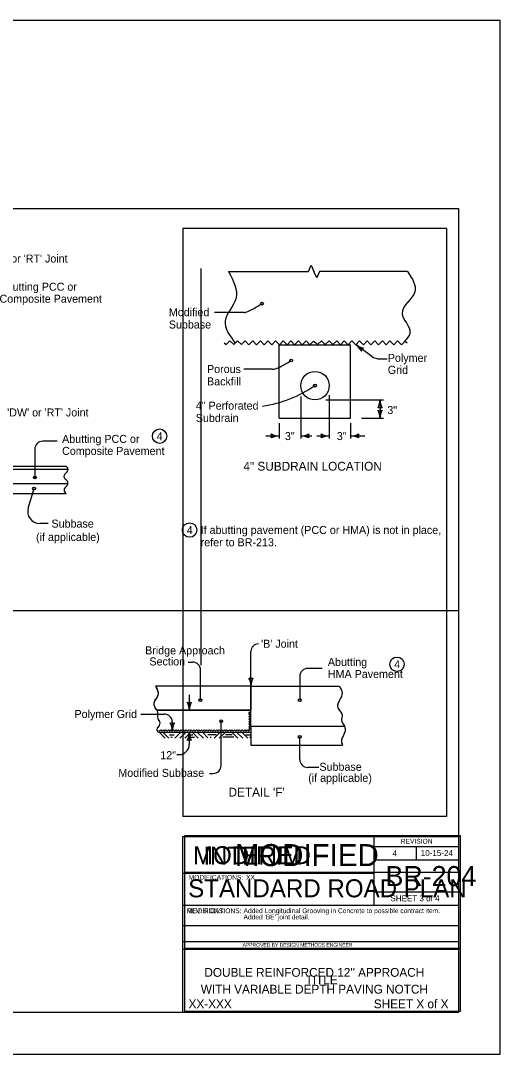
# Model space of a CAD drawing. Extents: x -2135039 to -2120895, y -2139150 to -2136566.
# Drawn here: x -2125693 to -2124495, y -2139150 to -2136566 of the extents above; entities that cross this region are included whole.
import ezdxf

# ---------------------------------------------------------------- set-up
doc = ezdxf.new("R2010")
doc.units = 0
for name, color, linetype in [('dsnDOTLogo', 7, 'Continuous'), ('dsnNonPlotable', 7, 'Continuous'), ('dsnStdBlock', 7, 'Continuous'), ('dsnstdblockInterim', 7, 'Continuous'), ('dsnStdLabel', 7, 'Continuous'), ('dsnStdLineWork', 7, 'Continuous'), ('dsnStdLogo', 7, 'Continuous'), ('dsnstdModifiedBlock', 7, 'Continuous'), ('dsnStdNote', 7, 'Continuous'), ('Level 1', 7, 'Continuous'), ('Level 2', 7, 'Continuous'), ('Level 3', 7, 'Continuous')]:
    doc.layers.add(name, color=color, linetype=linetype)

msp = doc.modelspace()

# ---------------------------------------------------------------- linework, layer by layer
at = {"layer": 'dsnDOTLogo'}
msp.add_lwpolyline([(-2127839, -2139150.4), (-2124495, -2139150.4), (-2124495, -2136566.4), (-2127839, -2136566.4)], close=True, dxfattribs=at)
at = {"layer": 'dsnNonPlotable'}
for p, q in [((-2125287.5, -2137085.9), (-2125287.5, -2138555.9)), ((-2124629.5, -2137085.9), (-2125287.5, -2137085.9)), ((-2124629.5, -2137085.9), (-2124629.5, -2138555.9)), ((-2125242.5, -2137185.9), (-2125242.5, -2138177.5)), ((-2127734.5, -2138040.9), (-2124599.5, -2138040.9)), ((-2124629.5, -2138555.9), (-2125287.5, -2138555.9))]:
    msp.add_line(p, q, dxfattribs=at)
at = {"layer": 'dsnStdLabel'}
for p, q in [((-2125601.3, -2137617.9), (-2125637.8, -2137617.9)), ((-2125657.6, -2137637.7), (-2125657.6, -2137709)), ((-2125673.9, -2137785), (-2125659.4, -2137736.1)), ((-2125623.8, -2137823.2), (-2125645.5, -2137823.2)), ((-2125117.7, -2138229.8), (-2125117.7, -2138143)), ((-2125274.1, -2138170), (-2125263.4, -2138170)), ((-2125243.6, -2138265), (-2125243.6, -2138189.8)), ((-2124939.7, -2138185.9), (-2124976.1, -2138185.9)), ((-2124995.9, -2138205.7), (-2124995.9, -2138265)), ((-2125271.8, -2138251.9), (-2125271.8, -2138290.3)), ((-2125392.4, -2138299.9), (-2125333.9, -2138299.9)), ((-2125314.1, -2138319.7), (-2125314.1, -2138341.9)), ((-2125192.1, -2138428.4), (-2125192.1, -2138317.9)), ((-2125271.8, -2138345.9), (-2125271.8, -2138376.1)), ((-2124995.9, -2138413.4), (-2124995.9, -2138357)), ((-2125302.5, -2138401.1), (-2125296.8, -2138401.1)), ((-2124948.1, -2138433.2), (-2124976.1, -2138433.2)), ((-2125221, -2138448.2), (-2125211.9, -2138448.2))]:
    msp.add_line(p, q, dxfattribs=at)
for centre in [(-2125657.6, -2137708.4), (-2125659.4, -2137736.1), (-2125244, -2138265), (-2124995.9, -2138265), (-2125192.1, -2138317.9), (-2124995.9, -2138357)]:
    msp.add_circle(centre, 3.46, dxfattribs=at)
for centre, radius, start, end in [((-2124881.3, -2137410.4), 42.5, 25.1788, 53.2513), ((-2124830.5, -2137342.2), 42.5, 233.2513, 261.3238), ((-2124827.4, -2137397.6), 16.4, 125.5179, 160.9846), ((-2125637.8, -2137637.7), 19.8, 90, 180), ((-2125645.5, -2137793.5), 29.7, 163.4172, 270), ((-2125099.2, -2138143), 18.6, 90, 180), ((-2125263.4, -2138189.8), 19.8, 0, 90), ((-2124976.1, -2138205.7), 19.8, 90, 180), ((-2125117.7, -2138193.9), 16.5, 252.2666, 287.7333), ((-2125160.5, -2138229.8), 42.7, 360, 28.0725), ((-2125117.7, -2138193.9), 16.5, 252.2666, 287.7333), ((-2125160.5, -2138229.8), 42.7, 360, 28.0725), ((-2125075, -2138229.8), 42.7, 151.9275, 180), ((-2125075, -2138229.8), 42.7, 151.9275, 180), ((-2125271.8, -2138254.5), 16.5, 252.2666, 287.7333), ((-2125314.6, -2138290.3), 42.7, 360, 28.0725), ((-2125229.1, -2138290.3), 42.7, 151.9275, 180), ((-2125333.9, -2138319.7), 19.8, 0, 90), ((-2125314.1, -2138306.1), 16.5, 252.2667, 287.7334), ((-2125356.8, -2138341.9), 42.7, 0, 28.0725), ((-2125271.3, -2138341.9), 42.7, 151.9275, 180), ((-2125314.6, -2138345.9), 42.7, 331.9275, 360), ((-2125229.1, -2138345.9), 42.7, 180, 208.0725), ((-2125271.8, -2138381.8), 16.5, 72.2666, 107.7334), ((-2125211.9, -2138428.4), 19.8, 270, 360), ((-2124976.1, -2138413.4), 19.8, 180, 270)]:
    msp.add_arc(centre, radius, start, end, dxfattribs=at)
at = {"layer": 'dsnStdLineWork'}
for p, q in [((-2125750.3, -2137679.9), (-2125579.5, -2137679.9)), ((-2125750.3, -2137688), (-2125574.6, -2137688)), ((-2125574.7, -2137724.5), (-2125750.3, -2137724.5)), ((-2125750.3, -2137748.2), (-2125579.5, -2137748.2)), ((-2125117.7, -2138230.3), (-2125355.8, -2138230.3)), ((-2125117.7, -2138230.3), (-2124896.8, -2138230.3)), ((-2125117.7, -2138230.3), (-2125117.7, -2138290.3)), ((-2125117.7, -2138290.3), (-2125352.7, -2138290.3)), ((-2125117.7, -2138330.3), (-2125117.7, -2138290.3)), ((-2125117.7, -2138330.3), (-2124883.9, -2138330.3)), ((-2125117.7, -2138330.3), (-2125117.7, -2138377.6)), ((-2125118.2, -2138346.2), (-2125345.7, -2138346.2)), ((-2125345.7, -2138346.2), (-2125331.7, -2138360.2)), ((-2125336.7, -2138346.2), (-2125322.7, -2138360.2)), ((-2125309.2, -2138352.4), (-2125321.1, -2138352.4)), ((-2125317.6, -2138357.3), (-2125314.4, -2138357.3)), ((-2125216.7, -2138346.2), (-2125315.3, -2138346.2)), ((-2125293.9, -2138346.2), (-2125307.9, -2138360.2)), ((-2125281.5, -2138346.4), (-2125295.5, -2138360.4)), ((-2125268.7, -2138346.2), (-2125282.7, -2138360.2)), ((-2125273, -2138357.4), (-2125259, -2138357.4)), ((-2125269.2, -2138351.6), (-2125262.8, -2138351.6)), ((-2125263.3, -2138346.2), (-2125249.3, -2138360.2)), ((-2125250.4, -2138346.4), (-2125236.4, -2138360.4)), ((-2125238.1, -2138346.2), (-2125225.3, -2138359)), ((-2125204.8, -2138351.6), (-2125225, -2138351.6)), ((-2125219.9, -2138357.3), (-2125216.7, -2138357.3)), ((-2125195.3, -2138346.2), (-2125209.3, -2138360.2)), ((-2125183, -2138346.4), (-2125197, -2138360.4)), ((-2125160.4, -2138357.4), (-2125188.2, -2138357.4)), ((-2125164.2, -2138351.6), (-2125181.3, -2138351.6)), ((-2125164.8, -2138346.2), (-2125150.8, -2138360.2)), ((-2125151.9, -2138346.4), (-2125137.9, -2138360.4)), ((-2125139.5, -2138346.2), (-2125125.6, -2138360.2)), ((-2125130.1, -2138351.6), (-2125118.2, -2138351.6)), ((-2125121.4, -2138357.3), (-2125118.2, -2138357.3)), ((-2125117.7, -2138377.6), (-2124888.9, -2138377.6))]:
    msp.add_line(p, q, dxfattribs=at)
for points in [[(-2125120.5, -2138296.9), (-2125123.1, -2138294.3)], [(-2125121, -2138339.8), (-2125122.8, -2138337.9), (-2125119.7, -2138334.7), (-2125122.8, -2138331.5), (-2125119.7, -2138328.4), (-2125122.8, -2138325.2), (-2125119.6, -2138322), (-2125122.8, -2138318.9), (-2125119.6, -2138315.7), (-2125122.8, -2138312.5), (-2125119.6, -2138309.4), (-2125122.8, -2138306.2), (-2125119.6, -2138303), (-2125122.8, -2138299.9), (-2125120.5, -2138296.9)], [(-2125347.5, -2138340.8), (-2125346, -2138342.4), (-2125342.8, -2138339.2), (-2125339.6, -2138342.4), (-2125336.4, -2138339.2), (-2125333.3, -2138342.4), (-2125330.1, -2138339.3), (-2125326.9, -2138342.4), (-2125323.8, -2138339.3), (-2125320.6, -2138342.5), (-2125317.4, -2138339.3), (-2125314.3, -2138342.5), (-2125311.1, -2138339.3), (-2125307.9, -2138342.5), (-2125304.8, -2138339.3), (-2125301.6, -2138342.5), (-2125298.4, -2138339.3), (-2125295.3, -2138342.5), (-2125292.1, -2138339.4), (-2125288.9, -2138342.5), (-2125285.8, -2138339.4), (-2125282.6, -2138342.5), (-2125279.4, -2138339.4), (-2125276.3, -2138342.6), (-2125273.1, -2138339.4), (-2125271.7, -2138340.5)], [(-2125271.3, -2138340.9), (-2125269.7, -2138342.5), (-2125266.6, -2138339.4), (-2125263.4, -2138342.5), (-2125260.2, -2138339.4), (-2125257.1, -2138342.6), (-2125253.9, -2138339.4), (-2125250.7, -2138342.6), (-2125247.5, -2138339.4), (-2125244.4, -2138342.6), (-2125241.2, -2138339.4), (-2125238.1, -2138342.6), (-2125234.9, -2138339.4), (-2125231.7, -2138342.6), (-2125228.5, -2138339.5), (-2125225.4, -2138342.6), (-2125222.2, -2138339.5), (-2125219, -2138342.7), (-2125215.9, -2138339.5), (-2125212.7, -2138342.7), (-2125209.5, -2138339.5), (-2125206.4, -2138342.7), (-2125203.2, -2138339.5), (-2125200, -2138342.7), (-2125196.9, -2138339.5), (-2125195.1, -2138341)], [(-2125195.1, -2138341), (-2125193.5, -2138342.5), (-2125190.3, -2138339.4), (-2125187.1, -2138342.6), (-2125184, -2138339.4), (-2125180.8, -2138342.6), (-2125177.6, -2138339.4), (-2125174.5, -2138342.6), (-2125171.3, -2138339.4), (-2125168.1, -2138342.6), (-2125165, -2138339.4), (-2125161.8, -2138342.6), (-2125158.6, -2138339.5), (-2125155.5, -2138342.6), (-2125152.3, -2138339.5), (-2125149.1, -2138342.7), (-2125145.9, -2138339.5), (-2125142.8, -2138342.7), (-2125139.6, -2138339.5), (-2125136.5, -2138342.7), (-2125133.3, -2138339.5), (-2125130.1, -2138342.7), (-2125126.9, -2138339.6), (-2125123.8, -2138342.7), (-2125120.9, -2138339.8)]]:
    msp.add_lwpolyline(points, dxfattribs=at)
for points in [[(-2125355.8, -2138229.5), (-2125349.7, -2138244.8), (-2125349.8, -2138251.8), (-2125359.6, -2138271), (-2125358.2, -2138282.3), (-2125351.7, -2138292.4), (-2125351.1, -2138307.9), (-2125345.7, -2138318.8)], [(-2124896.8, -2138230.3), (-2124890.2, -2138246.7), (-2124896.3, -2138264.9), (-2124900.9, -2138274.8), (-2124899.4, -2138287), (-2124889.5, -2138303.7), (-2124891.8, -2138314.4), (-2124883.9, -2138330.3), (-2124887.2, -2138354.7), (-2124891.8, -2138365.3), (-2124888.9, -2138377.6)], [(-2125345.7, -2138318.8), (-2125345.7, -2138325.3), (-2125352.2, -2138335.5)], [(-2125352.2, -2138335.5), (-2125352.2, -2138341.9), (-2125345.7, -2138346.2)]]:
    msp.add_spline(points, degree=3, dxfattribs=at)
at = {"layer": 'dsnStdLogo'}
for p, q in [((-2124810.4, -2138605.9), (-2124810.4, -2138697.3)), ((-2124810.4, -2138630.9), (-2124599.5, -2138630.9)), ((-2124704.9, -2138630.9), (-2124704.9, -2138664.1)), ((-2124810.4, -2138664.1), (-2124599.5, -2138664.1)), ((-2125287.5, -2138697.3), (-2124810.4, -2138697.3)), ((-2124810.4, -2138697.3), (-2124810.4, -2138777.3)), ((-2124599.5, -2138745.1), (-2124810.4, -2138745.1)), ((-2125287.5, -2138777.3), (-2124599.5, -2138777.3)), ((-2125287.5, -2138828.3), (-2124599.5, -2138828.3)), ((-2125287.5, -2138868.3), (-2124599.5, -2138868.3)), ((-2125287.5, -2138887.3), (-2124599.5, -2138887.3))]:
    msp.add_line(p, q, dxfattribs=at)
msp.add_lwpolyline([(-2125287.5, -2138605.9), (-2124599.5, -2138605.9), (-2124599.5, -2139045.9), (-2125287.5, -2139045.9)], close=True, dxfattribs=at)
at = {"layer": 'dsnstdModifiedBlock'}
for p, q in [((-2125283.2, -2138695), (-2124595.1, -2138695)), ((-2125283.2, -2138885), (-2124595.1, -2138885))]:
    msp.add_line(p, q, dxfattribs=at)
msp.add_lwpolyline([(-2125283.2, -2138603.7), (-2124595.1, -2138603.7), (-2124595.1, -2139043.7), (-2125283.2, -2139043.7)], close=True, dxfattribs=at)
at = {"layer": 'dsnStdNote'}
for centre in [(-2125345.9, -2137605.2), (-2124752.9, -2138175.4)]:
    msp.add_circle(centre, 18, dxfattribs=at)
at = {"layer": 'Level 1'}
msp.add_lwpolyline([(-2127734.5, -2137035.9), (-2124599.5, -2137035.9), (-2124599.5, -2139045.9), (-2127734.5, -2139045.9)], close=True, dxfattribs=at)
at = {"layer": 'Level 2'}
for p, q in [((-2125134.2, -2137295.9), (-2125208.4, -2137295.9)), ((-2125046.9, -2137560.4), (-2125046.9, -2137377)), ((-2125046.9, -2137377), (-2124868.7, -2137377)), ((-2124868.7, -2137560.4), (-2124868.7, -2137377)), ((-2125064.3, -2137438), (-2125135.6, -2137438)), ((-2125046.9, -2137560.4), (-2124868.7, -2137560.4)), ((-2125577, -2137682.4), (-2125579.5, -2137679.9)), ((-2125582, -2137699.5), (-2125577, -2137694.5)), ((-2125579.5, -2137714.1), (-2125582, -2137711.6)), ((-2125582, -2137733.7), (-2125577, -2137728.7)), ((-2125577, -2137716.6), (-2125579.5, -2137714.1)), ((-2125579.5, -2137748.2), (-2125582, -2137745.7)), ((-2125117.7, -2138230.3), (-2125355.4, -2138230.3)), ((-2125117.7, -2138290.3), (-2125117.7, -2138230.3)), ((-2125352.7, -2138290.3), (-2125117.7, -2138290.3))]:
    msp.add_line(p, q, dxfattribs=at)
for points in [[(-2125173.7, -2137193.6), (-2124973.9, -2137193.6), (-2124967.1, -2137177.8), (-2124960.3, -2137193.6)], [(-2124726.7, -2137193.6), (-2124946.8, -2137193.6), (-2124953.5, -2137209.4), (-2124960.3, -2137193.6)], [(-2125184.4, -2137371.4), (-2125179.7, -2137376.2), (-2125170.1, -2137366.7), (-2125160.7, -2137376.2), (-2125151.1, -2137366.8), (-2125141.6, -2137376.3), (-2125132.1, -2137366.8), (-2125122.6, -2137376.4), (-2125113.1, -2137366.9), (-2125103.6, -2137376.4), (-2125094.1, -2137366.9), (-2125084.6, -2137376.5), (-2125075.1, -2137367), (-2125065.6, -2137376.5), (-2125056.1, -2137367), (-2125046.6, -2137376.5), (-2125037.1, -2137367.1), (-2125027.6, -2137376.6), (-2125018.1, -2137367.1), (-2125008.6, -2137376.6), (-2124999, -2137367.2), (-2124989.6, -2137376.7), (-2124980.1, -2137367.2), (-2124970.6, -2137376.8), (-2124961.1, -2137367.3), (-2124955.3, -2137371.8)], [(-2124955.8, -2137371.4), (-2124951.1, -2137376.2), (-2124941.5, -2137366.7), (-2124932.1, -2137376.2), (-2124922.5, -2137366.8), (-2124913.1, -2137376.3), (-2124903.6, -2137366.8), (-2124894.1, -2137376.4), (-2124884.5, -2137366.9), (-2124875.1, -2137376.4), (-2124865.5, -2137366.9), (-2124856, -2137376.5), (-2124846.5, -2137367), (-2124837, -2137376.5), (-2124827.5, -2137367), (-2124818, -2137376.5), (-2124808.5, -2137367.1), (-2124799, -2137376.6), (-2124789.5, -2137367.1), (-2124780, -2137376.6), (-2124770.5, -2137367.2), (-2124761, -2137376.7), (-2124751.5, -2137367.2), (-2124742, -2137376.8), (-2124732.5, -2137367.3), (-2124727.3, -2137371.4)]]:
    msp.add_lwpolyline(points, dxfattribs=at)
for centre, radius in [((-2125090.1, -2137273.9), 3.46), ((-2125017.2, -2137416.1), 3.46), ((-2124957.8, -2137478.8), 35.6), ((-2124957.8, -2137478.8), 3.46), ((-2125270.8, -2137839.9), 18)]:
    msp.add_circle(centre, radius, dxfattribs=at)
for centre, radius, start, end in [((-2125134.2, -2137285.9), 10, 270, 291.4956), ((-2125204.2, -2137108.3), 200.9, 291.4956, 304.4007), ((-2125131.3, -2137250.4), 200.9, 292.4048, 304.4007), ((-2125064.3, -2137413), 25, 270, 292.4048), ((-2125135.5, -2137219.4), 314.4, 278.602, 304.4007), ((-2124837.7, -2137514.4), 42.5, 331.9275, 360), ((-2124752.7, -2137514.4), 42.5, 180, 208.0725), ((-2124795.2, -2137550.1), 16.4, 72.2666, 107.7334), ((-2124795.2, -2137524.4), 16.4, 252.2666, 287.7333), ((-2124837.7, -2137560), 42.5, 360, 28.0725), ((-2124752.7, -2137560), 42.5, 151.9275, 180), ((-2125082.6, -2137604.4), 16.4, 342.2666, 17.7333), ((-2125046.9, -2137561.9), 42.5, 241.9275, 270), ((-2125046.9, -2137646.9), 42.5, 90, 118.0725), ((-2124993.5, -2137561.9), 42.5, 270, 298.0725), ((-2124993.5, -2137561.9), 42.5, 270, 298.0725), ((-2124993.5, -2137646.9), 42.5, 61.9275, 90), ((-2124993.5, -2137646.9), 42.5, 61.9275, 90), ((-2124957.8, -2137604.4), 16.4, 162.2666, 197.7334), ((-2124957.8, -2137604.4), 16.4, 162.2666, 197.7334), ((-2124957.8, -2137604.4), 16.4, 342.2666, 17.7333), ((-2124922.2, -2137561.9), 42.5, 241.9275, 270), ((-2124957.8, -2137604.4), 16.4, 342.2666, 17.7333), ((-2124922.2, -2137561.9), 42.5, 241.9275, 270), ((-2124922.2, -2137646.9), 42.5, 90, 118.0725), ((-2124922.2, -2137646.9), 42.5, 90, 118.0725), ((-2124868.7, -2137561.9), 42.5, 270, 298.0725), ((-2124868.7, -2137646.9), 42.5, 61.9275, 90), ((-2124833.1, -2137604.4), 16.4, 162.2666, 197.7334), ((-2125583.1, -2137688.4), 8.56, 315, 45), ((-2125576, -2137705.6), 8.56, 135, 225), ((-2125576, -2137739.7), 8.53, 135, 225), ((-2125583.1, -2137722.7), 8.53, 315, 45), ((-2125296.8, -2138376.1), 25, 270, 0)]:
    msp.add_arc(centre, radius, start, end, dxfattribs=at)
for points in [[(-2125173.7, -2137193.6), (-2125155.2, -2137261.4), (-2125182.3, -2137317), (-2125157.6, -2137371.4)], [(-2124726.7, -2137193.6), (-2124708.2, -2137244.1), (-2124740.3, -2137298.5), (-2124720.5, -2137345.5), (-2124735.3, -2137368.9)]]:
    msp.add_spline(points, degree=3, dxfattribs=at)
msp.add_open_spline([(-2125355.4, -2138230.3), (-2125353.5, -2138235.1), (-2125351.6, -2138240), (-2125349.7, -2138244.8), (-2125348.8, -2138247), (-2125349.4, -2138249.6), (-2125349.8, -2138251.8), (-2125351.2, -2138258.7), (-2125358.4, -2138264.3), (-2125359.6, -2138271), (-2125360.2, -2138274.6), (-2125359.5, -2138278.8), (-2125358.2, -2138282.3), (-2125357.1, -2138285.3), (-2125354.3, -2138287.6), (-2125352.7, -2138290.3)], degree=3, dxfattribs=at)
at = {"layer": 'Level 3'}
for p, q in [((-2124816.1, -2137406.1), (-2124855.9, -2137376.3)), ((-2124795.5, -2137411.8), (-2124777.2, -2137411.8)), ((-2124993.5, -2137506.2), (-2124993.5, -2137611)), ((-2124922.2, -2137502.8), (-2124922.2, -2137611)), ((-2124930.4, -2137514.4), (-2124786.9, -2137514.4)), ((-2124795.2, -2137514.4), (-2124795.2, -2137560)), ((-2125046.9, -2137572.4), (-2125046.9, -2137611)), ((-2124868.7, -2137572.4), (-2124868.7, -2137611)), ((-2124841.3, -2137560), (-2124786.9, -2137560)), ((-2125080.3, -2137604.4), (-2125046.9, -2137604.4)), ((-2124993.5, -2137604.4), (-2124965.6, -2137604.4)), ((-2124953.3, -2137604.4), (-2124922.2, -2137604.4)), ((-2124868.7, -2137604.4), (-2124833.5, -2137604.4))]:
    msp.add_line(p, q, dxfattribs=at)
msp.add_arc((-2124795.5, -2137372.2), 39.6, 238.7046, 270, dxfattribs=at)

# ---------------------------------------------------------------- texts
at = {"layer": 'dsnNonPlotable'}
msp.add_text('REVISIONS:', height=12, dxfattribs=at).set_placement((-2125277.5, -2138797.6))
at = {"layer": 'dsnStdBlock'}
for s, height, p in [('MODIFIED', 45, (-2125262.4, -2138675.1)), ('MODIFICATIONS:', 12, (-2125277.5, -2138797.6))]:
    msp.add_text(s, height=height, dxfattribs=at).set_placement(p)
at = {"layer": 'dsnstdblockInterim'}
msp.add_text('INTERIM', height=45, dxfattribs=at).set_placement((-2125236.5, -2138676.3))
at = {"layer": 'dsnStdLabel'}
for s, p in [("'DW' or 'RT' Joint", (-2125778.7, -2137171.1)), ('Abutting PCC or', (-2125745.6, -2137241.5)), ('Composite Pavement', (-2125745.6, -2137271.5)), ("'DW' or 'RT' Joint", (-2125726.4, -2137555.8)), ('Abutting PCC or', (-2125589.3, -2137622)), ('Composite Pavement', (-2125589.3, -2137652)), ('Subbase', (-2125615.8, -2137833.7)), ('(if applicable)', (-2125654.3, -2137867.2)), ("'B' Joint", (-2125092.3, -2138134)), ('Bridge Approach', (-2125382, -2138150.6)), ('Section', (-2125371.2, -2138178.3)), ('Abutting', (-2124925.6, -2138179.6)), ('HMA Pavement', (-2124925.6, -2138209.6)), ('Polymer Grid', (-2125558.3, -2138309.7)), ('12"', (-2125344.1, -2138412.6)), ('Modified Subbase', (-2125448.8, -2138456.8)), ('Subbase', (-2124946.7, -2138441.6)), ('(if applicable)', (-2124974.7, -2138469.3))]:
    msp.add_text(s, height=20, dxfattribs=at).set_placement(p)
at = {"layer": 'dsnStdLogo'}
for s, height, p in [('REVISION', 12, (-2124743.4, -2138623.8)), ('4', 15, (-2124764, -2138655.3)), ('10-15-24', 15, (-2124693.6, -2138654.8)), ('BR-204', 50, (-2124781.6, -2138729.8)), ('STANDARD ROAD PLAN', 45.001, (-2125274.4, -2138757.9)), ('SHEET 3 of 4', 15, (-2124769.4, -2138767.9)), ('Added Longitudinal Grooving in Concrete to possible contract item. ', 12, (-2125136.2, -2138797.5)), ("Added 'BE' joint detail.", 12, (-2125136.2, -2138813.1)), ('APPROVED BY DESIGN METHODS ENGINEER', 9.003, (-2125138.5, -2138881.4)), ("DOUBLE REINFORCED 12'' APPROACH", 22, (-2125234, -2138956.6)), ('WITH VARIABLE DEPTH PAVING NOTCH', 22, (-2125242.9, -2138998.6))]:
    msp.add_text(s, height=height, dxfattribs=at).set_placement(p)
at = {"layer": 'dsnstdModifiedBlock'}
for s, height, p in [('MODIFIED', 55, (-2125158.1, -2138679.9)), ('MODIFICATIONS:', 12, (-2125273.2, -2138713.9)), ('XX', 12, (-2125129.9, -2138713.9)), ('TITLE', 22, (-2124981.1, -2138975.4)), ('XX-XXX', 22, (-2125273.5, -2139035.3)), ('SHEET X of X', 22, (-2124810.8, -2139035.3))]:
    msp.add_text(s, height=height, dxfattribs=at).set_placement(p)
at = {"layer": 'dsnStdNote'}
for p in [(-2125353, -2137615.2), (-2124760, -2138185.4)]:
    msp.add_text('4', height=20, dxfattribs=at).set_placement(p)
at = {"layer": 'Level 1'}
for s, p in [('If abutting pavement (PCC or HMA) is not in place, ', (-2125243.2, -2137849.6)), ('refer to BR-213.', (-2125243.2, -2137880.4))]:
    msp.add_text(s, height=20, dxfattribs=at).set_placement(p)
at = {"layer": 'Level 2'}
for s, height, p in [('4" SUBDRAIN LOCATION', 22, (-2125136.5, -2137691.3)), ('4', 20, (-2125278, -2137849.9))]:
    msp.add_text(s, height=height, dxfattribs=at).set_placement(p)
at = {"layer": 'Level 3'}
for s, height, p in [('Modified', 20, (-2125322.7, -2137305.2)), ('Subbase', 20, (-2125322.7, -2137336)), ('Polymer ', 20, (-2124775.9, -2137419.4)), ('Porous', 20, (-2125227.4, -2137447.3)), ('Grid', 20, (-2124775.9, -2137449.4)), ('Backfill', 20, (-2125227.4, -2137478.2)), ('4" Perforated ', 20, (-2125255.4, -2137538.8)), ('3"', 20, (-2124777.1, -2137549.9)), ('Subdrain', 20, (-2125255.4, -2137569.6)), ('3"', 20, (-2125032.9, -2137614.9)), ('3"', 20, (-2124903.2, -2137614.9)), ("DETAIL 'F'", 22, (-2125173.6, -2138506))]:
    msp.add_text(s, height=height, dxfattribs=at).set_placement(p)

doc.saveas('drawing.dxf')
